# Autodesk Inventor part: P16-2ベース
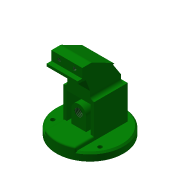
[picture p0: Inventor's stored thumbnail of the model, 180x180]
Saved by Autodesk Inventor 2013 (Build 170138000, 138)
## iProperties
Created: 2008-07
Part Number: P16-2ベース
Document SubType Name: Modeling
Designer: y-shimohigashi
Density: 1 g/cm^3
Material: 一般
Author: y-shimohigashi
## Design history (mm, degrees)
sketch "スケッチ2"
  geometry: C1 r 65 at (0, 0); 1 further point
  constraints: 1 centre point, 1 coincident
  dimensions: "d0" = 130 diameter of C1
extrude "押し出し1" new body sketch "スケッチ2" distance "d1" = 15; taper "d2" = 0 deg
sketch "スケッチ3"
  geometry: L1 (-65, 15)-(65, 15) reference; L2 (43, 15)-(43, 80); L3 (43, 80)-(38, 80); L4 (38, 80)-(38, 93); L5 (38, 93)-(16, 127); L6 (16, 127)-(-27, 149); L7 (-27, 149)-(-45, 149); L8 (-45, 149)-(-45, 131); L9 (-45, 131)-(-54, 131); L10 (-54, 131)-(-54, 126); L11 (-54, 126)-(-44, 126); L12 (-44, 126)-(-31, 119); L13 (-31, 119)-(-22, 95); L14 (-22, 95)-(-22, 15); L15 (-22, 15)-(43, 15); 1 further point
  constraints: 28 end point, 6 parallel, 3 perpendicular, 2 point on line, 1 collinear
  dimensions: "d3" = 43 distance from line of L2 point (0, 0); "d4" = 65 distance of L2.start L2.end; "d5" = 13 distance of L3.end L4.end; "d6" = 34 vertical distance of L4.end L5.end; "d7" = 22 vertical distance of L5.end L6.end; "d8" = 5 distance of L2.end L3.end; "d9" = 22 horizontal distance of L4.end L5.end; "d10" = 43 horizontal distance of L5.end L6.end; "d11" = 18 distance of L6.end L7.end; "d12" = 9 distance of L8.end L9.end; "d13" = 18 distance of L7.end L8.end; "d14" = 5 distance of L9.end L10.end; "d15" = 10 distance of L10.end L11.end; "d16" = 24 vertical distance of L12.end L13.end; "d17" = 80 distance of L13.end L14.end; "d18" = 65 distance between parallel lines of L2 L14; "d19" = 13 horizontal distance of L11.end L12.end
extrude "押し出し2" join sketch "スケッチ3" stored distance "d20" = 60; taper "d21" = 0 deg
sketch "スケッチ4"
  geometry: L1 (0, 0)-(60, 0) reference; L2 (60, 0)-(52, 0); L3 (52, 0)-(52, -45); L4 (52, -45)-(60, -45); L5 (60, -45)-(60, 0); L6 (0, 0)-(8, 0); L7 (8, 0)-(8, -45); L8 (8, -45)-(0, -45); L9 (0, -45)-(0, 0)
  constraints: 16 end point, 4 parallel, 2 collinear, 2 horizontal, 2 perpendicular
  dimensions: "d22" = 8 distance of L3.end L4.end; "d23" = 45 distance of L4.end L1.end
extrude "押し出し3" cut sketch "スケッチ4" stored distance "d24" = 60; taper "d25" = 0 deg
sketch "スケッチ5"
  geometry: L1 (60, -65)-(60, 0) reference; L2 (0, 0)-(60, 0) reference; L3 (0, 0)-(0, -65) reference; L4 (0, -65)-(60, -65) reference; L5 (53, -58)-(53, -7); L6 (53, -7)-(7, -7); L7 (7, -7)-(7, -58); L8 (7, -58)-(53, -58); L9 (44.5, -7)-(44.5, -32.5); L10 (15.5, -32.5)-(15.5, -7); A1 r 14.5 centre (30, -32.5) between (15.5, -32.5) and (44.5, -32.5); 2 further points
  constraints: 12 end point, 2 midpoint, 2 perpendicular, 2 point on circle, 2 point on line, 2 tangent, 1 centre point, 1 horizontal alignment, 1 vertical alignment, 3 other
  dimensions: "d26" = 7 distance between parallel lines of L3 L7; "d27" = 8.5 distance between parallel lines of L7 L10
extrude "押し出し4" cut sketch "スケッチ5" stored distance "d28" = 60; taper "d29" = 0 deg
hole "穴1" diameter "d32" = 15.294; stored, may be unused: countersink angle "d36" = 90 deg, drill point angle "d38" = 118 deg; dims "d30" = 10, "d31" = 10, "d33" = 6, "d34" = 4, "d35" = 2, "d37" = 8
sketch "スケッチ6"
  geometry: L1 (30, -22)-(-30, -22) reference; L2 (-30, -22)-(-30, -57.663); L3 (30, -22)-(30, -57.663); A1 r 65 centre (0, 0) between (-30, -57.663) and (30, -57.663) reference; A2 r 65 centre (0, 0) between (-30, -57.663) and (30, -57.663)
  constraints: 4 end point, 4 point on circle, 1 centre point, 1 concentric, 1 parallel, 1 perpendicular
extrude "押し出し5" join sketch "スケッチ6" stored distance "d39" = 60; taper "d40" = 0 deg
sketch "スケッチ7" dims "d41" = 106
  geometry: 3 further points
  constraints: 2 vertical alignment, 1 coincident, 2 other
hole "穴2" sketch "スケッチ7" at (0, 53) diameter "d42" = 8; stored, may be unused: countersink angle "d46" = 90 deg, drill point angle "d48" = 118 deg; dims "d43" = 6, "d44" = 4, "d45" = 2, "d47" = 8
pattern_circular "放射状パターン1" dims angle "d50" = 360 deg
sketch "スケッチ8"
  geometry: L1 (30, -178.8)-(30, 29.8) reference; L2 (60, -18)-(60, 0) reference; 3 further points
  constraints: 1 horizontal alignment, 1 midpoint, 1 symmetric about line
  dimensions: "d53" = 30 distance of point (15, -9) point (45, -9)
hole "穴3" sketch "スケッチ8" at (15, -9), (45, -9) diameter "d54" = 6.647; stored, may be unused: countersink angle "d58" = 90 deg, drill point angle "d60" = 118 deg; dims "d55" = 6, "d56" = 4, "d57" = 2, "d59" = 8
fillet "フィレット1" dims "d52" = 8
fillet "フィレット2" dims "d61" = 8
fillet "フィレット3" dims "d62" = 3
chamfer "面取り1" distance "d63" = 3; stored, may be unused: second distance "d64" = 2, angle "d65" = 45 deg
node "ソリッド1"
node "ソリッド ボディ"
node "サーフェス ボディ"
node "投影ループ1"
